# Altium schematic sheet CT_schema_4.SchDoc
size 295 x 165 mm
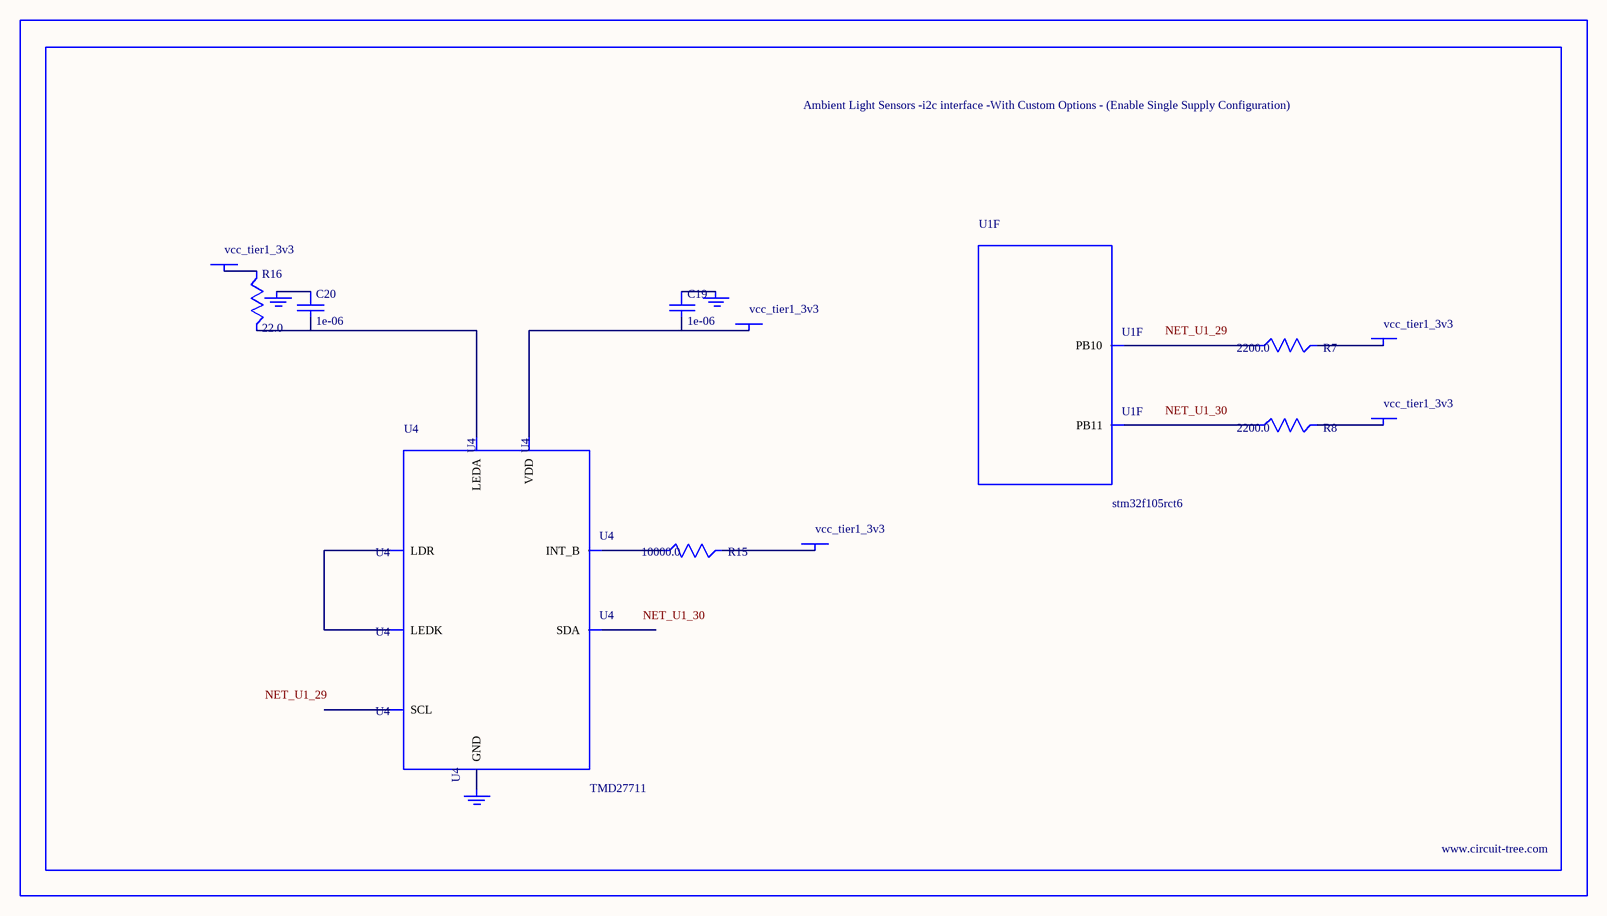
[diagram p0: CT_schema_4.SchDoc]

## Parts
BORDER3  (no value)
C19  1e-06  [C0603]
C20  1e-06  [C0603]
GND_INSTANCE_3_0  (no value)
GND_INSTANCE_3_1  (no value)
GND_INSTANCE_3_2  (no value)
POWER_INSTANCE_3_0  vcc_tier1_3v3
POWER_INSTANCE_3_1  vcc_tier1_3v3
POWER_INSTANCE_3_2  vcc_tier1_3v3
POWER_INSTANCE_3_3  vcc_tier1_3v3
POWER_INSTANCE_3_4  vcc_tier1_3v3
R7  2200.0  [R0603]
R8  2200.0  [R0603]
R15  10000.0  [R0603]
R16  22.0  [R0603]
U1  stm32f105rct6  [LQFP64]  (part F of 7)
U4  TMD27711  [SMD-8]

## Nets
NetC19_1: C19.1 GND_INSTANCE_3_0.0(GND)
NetC19_2: C19.2 POWER_INSTANCE_3_0.0(PWR) U4.1(VDD)
NetC20_1: C20.1 GND_INSTANCE_3_1.0(GND)
NetC20_2: C20.2 R16.2 U4.4(LEDA)
NetGND_INSTANCE_3_2_0: GND_INSTANCE_3_2.0(GND) U4.3(GND)
NetPOWER_INSTANCE_3_1_0: POWER_INSTANCE_3_1.0(PWR) R16.1
NetPOWER_INSTANCE_3_2_0: POWER_INSTANCE_3_2.0(PWR) R15.2
NetPOWER_INSTANCE_3_3_0: POWER_INSTANCE_3_3.0(PWR) R7.2
NetPOWER_INSTANCE_3_4_0: POWER_INSTANCE_3_4.0(PWR) R8.2
NetR7_1: R7.1 U1.29(PB10)
NetR8_1: R8.1 U1.30(PB11)
NetR15_1: R15.1 U4.7(INT_B)
NetU4_5: U4.5(LEDK) U4.6(LDR)

Not connected (* = marked no-connect by the designer): U4 2(SCL) 8(SDA)

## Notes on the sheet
- Labels drawn without touching a wire or pin: NET_U1_29, NET_U1_30

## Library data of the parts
BORDER3 = BORDER_PAGE3
C19 C20 = C0603C105K3RACTU
GND_INSTANCE_3_0-GND_INSTANCE_3_2 = GND
POWER_INSTANCE_3_0-POWER_INSTANCE_3_4 = PWR
R7 R8 = RC0603JR-072K2L
R15 = RC0603JR-0710KL
R16 = RC0603JR-0722RL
